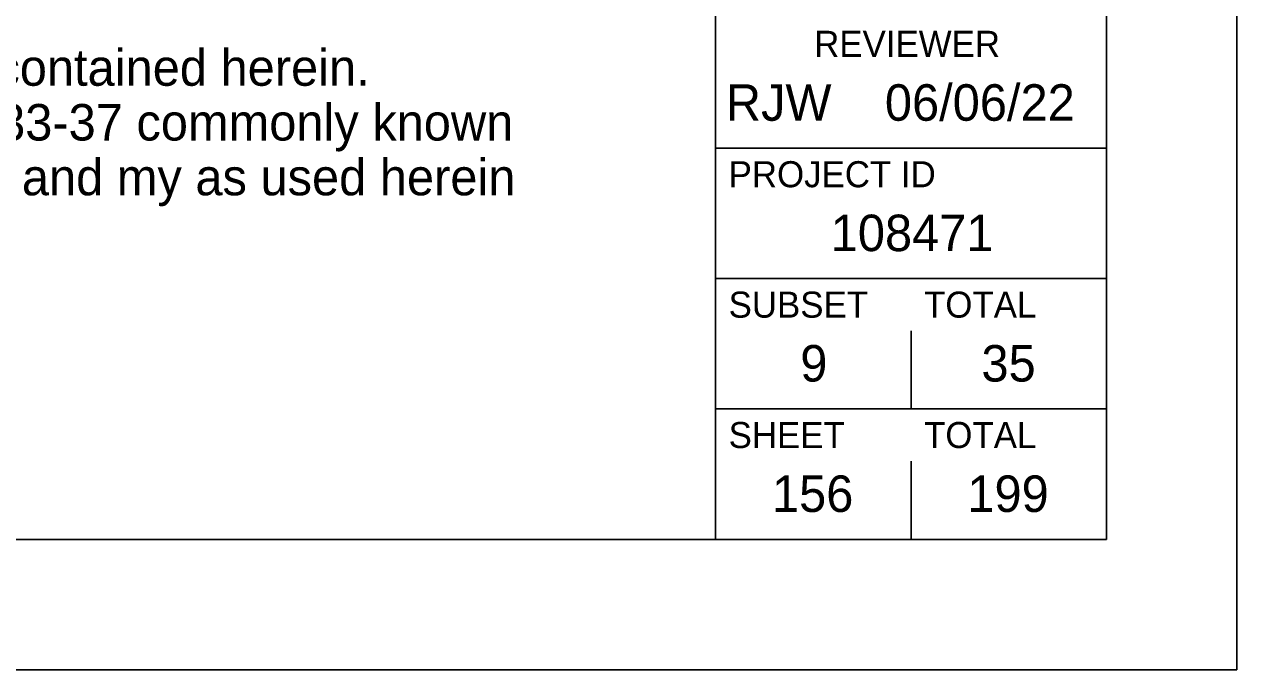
# Model space of a CAD drawing. Extents: x -6.7 to 34, y -3.7 to 22.
# Drawn here: x 29.347 to 34, y 0 to 2.475 of the extents above; entities that cross this region are included whole.
import ezdxf

# ---------------------------------------------------------------- set-up
doc = ezdxf.new("R2010")
doc.units = 0
for name, color, linetype in [('SH_Border', 7, 'Continuous'), ('SH_Data', 7, 'Continuous'), ('SH_Named_Boundary', 7, 'Continuous'), ('SH_Text', 7, 'Continuous')]:
    doc.layers.add(name, color=color, linetype=linetype)

msp = doc.modelspace()

# ---------------------------------------------------------------- linework, layer by layer
at = {"layer": 'SH_Border'}
for p, q in [((32, 0.5), (32, 21.5)), ((32, 2), (33.5, 2)), ((32, 1.5), (33.5, 1.5)), ((32, 1), (33.5, 1))]:
    msp.add_line(p, q, dxfattribs=at)
msp.add_lwpolyline([(1.5, 21.5), (33.5, 21.5), (33.5, 0.5), (1.5, 0.5)], close=True, dxfattribs=at)
at = {"layer": 'SH_Data'}
msp.add_lwpolyline([(0, 0), (34, 0), (34, 22), (0, 22)], close=True, dxfattribs=at)
at = {"layer": 'SH_Named_Boundary'}
for p, q in [((32.75, 1), (32.75, 1.3)), ((32.75, 0.5), (32.75, 0.8)), ((32.375, 0.675), (32.375, 0.675))]:
    msp.add_line(p, q, dxfattribs=at)

# ---------------------------------------------------------------- texts
for s, height, p in [('REVIEWER', 0.1, (32.3783, 2.35)), ('RJW', 0.14, (32.0393, 2.105)), ('06/06/22', 0.14, (32.6497, 2.105)), ('PROJECT ID', 0.1, (32.05, 1.85)), ('108471', 0.14, (32.4418, 1.605)), ('SUBSET', 0.1, (32.05, 1.35)), ('TOTAL', 0.1, (32.8, 1.35)), ('9', 0.14, (32.325, 1.105)), ('35', 0.14, (33.0202, 1.105)), ('SHEET', 0.1, (32.05, 0.85)), ('TOTAL', 0.1, (32.8, 0.85)), ('156', 0.14, (32.2163, 0.605)), ('199', 0.14, (32.9662, 0.605))]:
    msp.add_text(s, height=height, dxfattribs=at).set_placement(p)
at = {"layer": 'SH_Text'}
for s, p in [('locations of the existing property lines and centerline of existing Right of Way for property takes contained herein.  ', (21.3068, 2.2392)), ('All of my work contained herein was conducted in accordance with Ohio Administrative Code 4733-37 commonly known', (21.3068, 2.0292)), ('as "A Minimum Standards for Boundary Surveys in the State of Ohio" unless noted.  The words I and my as used herein', (21.3068, 1.8192))]:
    msp.add_text(s, height=0.14, dxfattribs=at).set_placement(p)

doc.saveas('drawing.dxf')
